// Mitsubishi GX Works2 project: code_plc_misu_xylanh   PLC: FX1S

PROGRAM MAIN
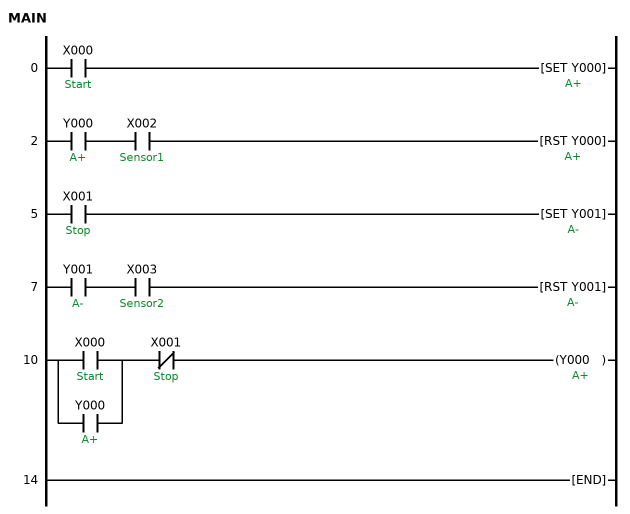
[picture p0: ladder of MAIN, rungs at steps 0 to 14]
0     LD      X000  ; Start
      SET     Y000  ; A+
2     LD      Y000  ; A+
      AND     X002  ; Sensor1
      RST     Y000  ; A+
5     LD      X001  ; Stop
      SET     Y001  ; A-
7     LD      Y001  ; A-
      AND     X003  ; Sensor2
      RST     Y001  ; A-
10    LD      X000  ; Start
      OR      Y000  ; A+
      ANI     X001  ; Stop
      OUT     Y000  ; A+
14    END
END_PROGRAM
